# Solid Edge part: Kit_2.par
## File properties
Sűrűség: 0,000 kg/m^3
Pontosság: 0,990
Author: ahadarics
Last saved by: ahadarics
Revision: 76
Username: ahadarics
Dokumentum tartalom típus: 0
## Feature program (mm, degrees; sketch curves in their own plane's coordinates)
base feature "unnamed BaseFeature 1"
sketch for "unnamed Hole 1" plane through (44.5, 44.5, 16.5) normal (0, 0, 1) x-axis (0, -1, 0)
  hole centre (0, 0) bore radius 4.188
hole "unnamed Hole 1" through
sketch for "unnamed Hole 2" plane through (44.5, 44.5, 16.5) normal (0, 0, 1) x-axis (0, -1, 0)
  hole centre (89, 0) bore radius 4.188
hole "unnamed Hole 2" through
sketch for "unnamed Hole 3" plane through (44.5, 44.5, 16.5) normal (0, 0, 1) x-axis (0, -1, 0)
  hole centre (89, -89) bore radius 4.188
hole "unnamed Hole 3" through
sketch for "unnamed Hole 4" plane through (44.5, 44.5, 16.5) normal (0, 0, 1) x-axis (0, -1, 0)
  hole centre (0, -89) bore radius 4.188
hole "unnamed Hole 4" through
pattern "unnamed Pattern 1" of "unnamed Hole 1", "unnamed Hole 2", "unnamed Hole 3", "unnamed Hole 4"
sketch for "Furat_5" plane through (56.5649, 0, 9.75) normal (0.999962, 0, 0.008727) x-axis (0, -1, 0)
  hole centre (0.0007, 0.7496) bore radius 4.283
  dimension (linear) = 0.0007
hole "Furat_5" diameter 8.566 finite
thread "unnamed Thread 1"
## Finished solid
Body 1: solid body, 293 faces, 731 edges, 456 vertices.
  Faces by surface: plane 143, cylinder 70, swept 56, cone 15, torus 8, spline 1
  Edges by curve: line 430, circle 140, spline 120, ellipse 28, curve on surface 12, intersection 1
Bounding box of the edges (mm; curved faces can reach further): 113.300 x 113.300 x 19.500, from (-56.65, -56.65, 0) to (56.65, 56.65, 19.5).
Cylindrical faces by radius (mm): R0.2 x48, R0.2006 x2, R0.2007 x2, R4.188 x4, R4.283 x1, R6 x1, R6.35 x4, R6.55 x4, R6.75 x4
Conical faces (half-angle, radius in mm at the cone's reference point): 0.5 deg R12.25 x4, 0.5 deg R35 x2, 45 deg R4.185 x4, 45 deg R4.985 x4, 45 deg R6.25 x1
Toroidal faces (ring radius, tube radius in mm): R6.05 r0.3 x2, R6.15 r0.2 x6
Planar faces by outward normal: +x 16, +y 16, +z 18, -x 14, -y 14, -z 1, oblique 64
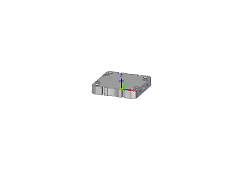
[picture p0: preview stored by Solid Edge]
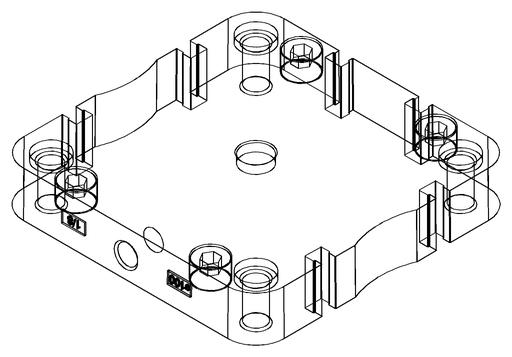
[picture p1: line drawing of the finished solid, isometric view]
